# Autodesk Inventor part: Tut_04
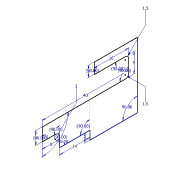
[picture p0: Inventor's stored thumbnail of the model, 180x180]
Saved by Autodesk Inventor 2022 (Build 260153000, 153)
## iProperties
Created: 2019-02
Part Number: Tut_04
Material: Generic
Document SubType Name: Modeling
Designer: LENOVO-CADCIM
Density: 1 g/cm^3
Appearance: Default
Author: LENOVO-CADCIM
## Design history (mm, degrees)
sketch "Sketch1"
  geometry: L1 (0, 0)-(0, 22); L2 (0, 0)-(22, 0); L3 (0, 22)-(4, 22); L4 (4, 22)-(4, 36); L5 (4, 22)-(18, 22); L6 (4, 36)-(8.333, 36); L7 (10.333, 38)-(10.333, 44); L8 (10.333, 36)-(16.333, 36); L9 (10.333, 44)-(16.333, 44); L10 (16.333, 44)-(16.333, 5.5); L11 (17.833, 4)-(23.833, 4); L12 (25.333, 5.5)-(25.333, 20); L13 (25.333, 20)-(30.333, 20); L14 (30.333, 20)-(30.333, 0); L15 (30.333, 0)-(0, 0); A1 r 2 centre (8.333, 38) between (8.333, 36) and (10.333, 38); A2 r 1.5 centre (23.833, 5.5) between (23.833, 4) and (25.333, 5.5); A3 r 1.5 centre (17.833, 5.5) between (16.333, 5.5) and (17.833, 4); 2 further points
  constraints: 30 end point, 9 perpendicular, 6 point on circle, 6 point on line, 6 tangent, 3 centre point, 3 horizontal, 2 vertical
  dimensions: "d0" = 90 deg angle of L2 L1; "d1" = 4 distance of L1.end L3.end; "d3" = 14 distance of L3.end L4.end; "d4" = 90 deg angle of L5 L4 (derived); "d5" = 90 deg angle of L4 L6; "d6" = 8 distance of L8.start L7.end; "d7" = 90 deg angle of L8 L7 (derived); "d8" = 6 distance of L7.end L9.end; "d9" = 90 deg angle of L7 L9 (derived); "d10" = 40 distance of L9.end point (16.333, 4); "d11" = 90 deg angle of L9 L10 (derived); "d12" = 9 distance of point (16.333, 4) point (25.333, 4); "d13" = 90 deg angle of L11 L10 (derived); "d14" = 16 distance of point (25.333, 4) L12.end; "d15" = 90 deg angle of L12 L11 (derived); "d16" = 5 distance of L12.end L13.end; "d17" = 90 deg angle of L12 L13 (derived); "d18" = 2 radius of A1 (derived); "d19" = 1.5 radius of A2 (derived); "d20" = 1.5 radius of A3 (derived)
